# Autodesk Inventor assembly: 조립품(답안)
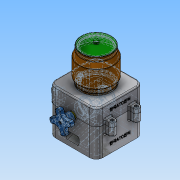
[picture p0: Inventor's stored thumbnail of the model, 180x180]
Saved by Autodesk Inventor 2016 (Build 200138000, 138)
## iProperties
Created: 2018-01
Part Number: 조립품(답안)
Material: 일반
Document SubType Name: Assembly
Designer: Administrator
Author: Administrator
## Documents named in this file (9)
- C:\Users\Administrator\Desktop\480107V1042\조립품(답안).iam
- C:\Users\Administrator\Desktop\480107V1042\본체(답안).ipt
- C:\Users\Administrator\Desktop\480107V1042\본체커버.ipt
- C:\Users\Administrator\Desktop\480107V1042\볼트 M3x12.ipt
- C:\Users\Administrator\Desktop\480107V1042\볼트 M4x12.ipt
- C:\Users\Administrator\Desktop\480107V1042\용기.ipt
- C:\Users\Administrator\Desktop\480107V1042\용기캡.ipt
- C:\Users\Administrator\Desktop\480107V1042\핸들.ipt
- C:\Users\Administrator\Desktop\480107V1042\핸들축.ipt
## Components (2 placed, 2 different names)
1. 핸들:1
2. 핸들축:1
